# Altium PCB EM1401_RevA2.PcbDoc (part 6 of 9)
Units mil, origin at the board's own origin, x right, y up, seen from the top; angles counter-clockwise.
Board outline 7800 x 5300 mil, 6 copper layers (Top Layer, MidLayer1, MidLayer2, MidLayer3, MidLayer4, Bottom Layer), stack 16.8 mil thick; 751 components, 531 nets, 2554 pads, 1388 vias.
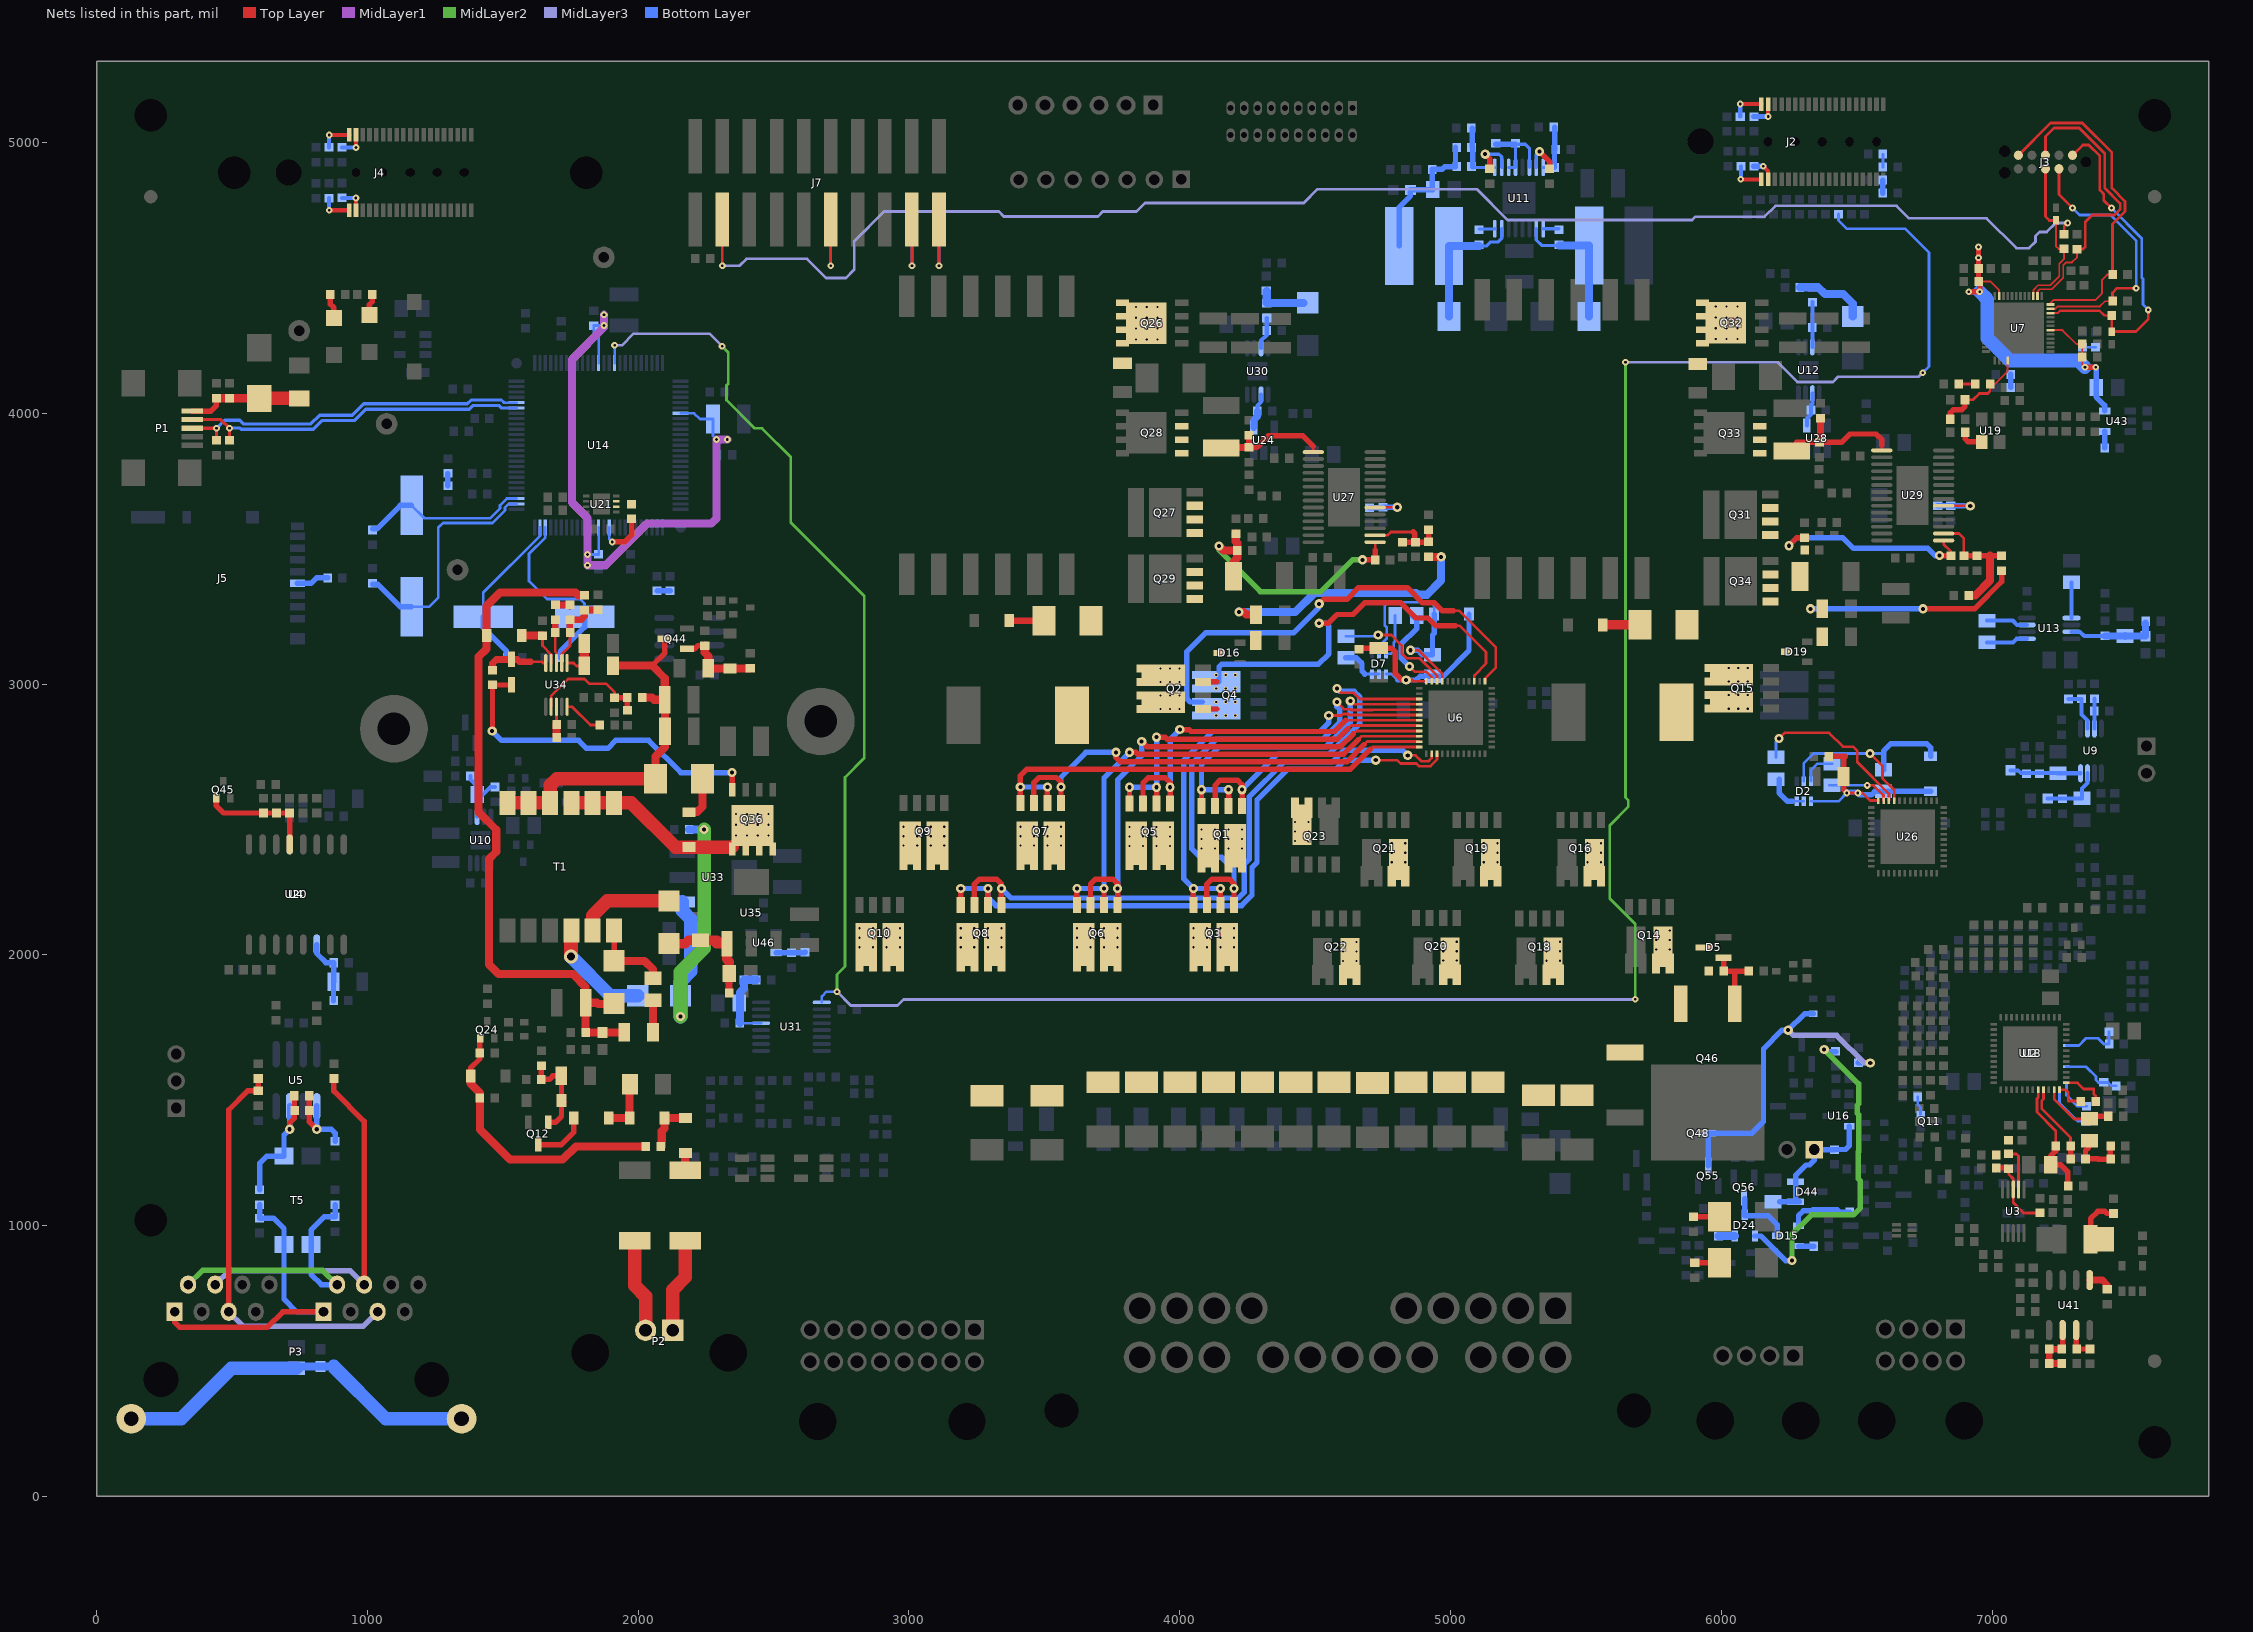
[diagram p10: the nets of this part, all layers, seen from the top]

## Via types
v1: diameter 25, hole 10, Top Layer to Bottom Layer, tented both sides, 275 vias
v2: diameter 16, hole 8, Top Layer to Bottom Layer, tented both sides, 240 vias
v3: diameter 34, hole 15, Top Layer to Bottom Layer, tented both sides, 158 vias
v4: diameter 34, hole 15, Top Layer to Bottom Layer, 154 vias
v5: diameter 34, hole 15, Top Layer to Bottom Layer, tented top, 95 vias
v6: diameter 34, hole 15, Top Layer to Bottom Layer, tented bottom, 89 vias
v7: diameter 25, hole 10, Top Layer to Bottom Layer, tented bottom, 75 vias
v8: diameter 25, hole 10, Top Layer to Bottom Layer, 62 vias
v9: diameter 28, hole 8, Top Layer to Bottom Layer, tented both sides, 60 vias
v10: diameter 24, hole 8, Top Layer to Bottom Layer, 53 vias
v11: diameter 25, hole 10, Top Layer to Bottom Layer, tented top, 28 vias
v12: diameter 50, hole 28, Top Layer to Bottom Layer, 28 vias
v13: diameter 25, hole 8, Top Layer to Bottom Layer, tented both sides, 18 vias
v14: diameter 50, hole 28, Top Layer to Bottom Layer, tented top, 12 vias
v15: diameter 25, hole 8, Top Layer to Bottom Layer, tented top, 9 vias
v16: diameter 20, hole 8, Top Layer to Bottom Layer, tented both sides, 9 vias
v17: diameter 24, hole 8, Top Layer to Bottom Layer, tented bottom, 4 vias
v18: diameter 24, hole 8, Top Layer to Bottom Layer, tented top, 4 vias
v19: diameter 28, hole 10, Top Layer to Bottom Layer, tented both sides, 3 vias
v20: diameter 35, hole 14, Top Layer to Bottom Layer, 3 vias
v21: diameter 50, hole 28, Top Layer to Bottom Layer, tented both sides, 2 vias
v22: diameter 50, hole 28, Top Layer to Bottom Layer, tented bottom, 2 vias
v23: diameter 30, hole 14, Top Layer to Bottom Layer, tented top, 2 vias
v24: diameter 28, hole 10, Top Layer to Bottom Layer, 1 vias
v25: diameter 35, hole 14, Top Layer to Bottom Layer, tented both sides, 1 vias
v26: diameter 35, hole 14, Top Layer to Bottom Layer, tented top, 1 vias

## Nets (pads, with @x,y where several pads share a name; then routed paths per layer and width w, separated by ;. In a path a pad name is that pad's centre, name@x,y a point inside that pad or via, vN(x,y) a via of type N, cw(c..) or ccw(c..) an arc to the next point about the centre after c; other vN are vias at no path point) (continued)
NCS_TS_: R284.2 U14.91 U31.1 | length 10656.6
  MidLayer2 w10: v8(2310,4248) 2332.65,4225.35 2332.65,4109.29 2326.5,4103.14 2326.5,4048.5 2430.5,3944.5 2458.02,3944.5 2563.5,3839.02 2563.5,3596.92 2835,3325.42 2835,2726.54 2764,2655.54 2764,1957.13 2734,1927.13 v11(2734,1864) ; v1(5646,4189) 5646,2581.43 5656,2571.43 5656,2546.57 5588,2478.57 5588,2209 5682,2115 v8(5682,1836)
  MidLayer3 w10: v1(1913,4251) 1940,4251 1983,4294 2264,4294 v8(2310,4248) ; v11(2734,1864) 2785,1813 2957.7,1813 2979.7,1835 5683,1835 v8(5682,1836) ; v1(5646,4189) 6208,4189 6281,4116 6412.12,4116 6431.12,4135 6729,4135 v8(6744,4150)
  Bottom Layer w10: v1(1913,4251) 1913.06,4250.94 U14.91@1913.06,4185.15 ; U31.1@2678.12,1824.57 2678.12,1846.12 2696,1864 v11(2734,1864) ; R284.2@6433,4735.88 6433,4712 6463,4682 6679.09,4682 6767,4594.09 6767,4173 v8(6744,4150)
NetC4_1: C4.1 C5.1 R19.1 U3.2 | length 174
  Top Layer w10: C4.1@7061.42,1265 7090.42,1265 7097.89,1257.53 U3.2@7097.89,1133.84
  Top Layer w20: C5.1@7014.98,1261.44 C5.1@7018.53,1265 ; C4.1@7057.86,1261.44 C4.1@7061.42,1265 C4.1@7060.91,1265.5
NetC4_2: C4.2 C251.1 R30.2 U3.3 | length 299.7
  Top Layer w10: C4.2@7061.42,1209.88 7061.42,1190 7078.21,1173.21 U3.3@7078.21,1133.84 7078.21,1085.21 7116.53,1046.88 R30.2@7177.42,1046.88
  Top Layer w20: C251.1@7018.53,1209.88 C251.1@7014.98,1213.44 7057.86,1213.44 C4.2@7061.42,1209.88
NetC8_1: C8.1 U2.37 | length 160.1
  Top Layer w10: U2.37@7274.55,1527.66 7315.39,1527.66 7338.05,1505 7375.42,1505 7375.42,1485.67 7382.42,1478.67 C8.1@7382.42,1458
NetC8_2: C8.2 U2.36 | length 116.7
  Top Layer w10: U2.36@7248.96,1502.07 7271.35,1502.07 7281.42,1492 7281.42,1460 7325.3,1460 C8.2@7327.3,1458 ; C8.2@7324.3,1462 C8.2@7325.3,1461
NetC10_1: C10.1 R271.1 U2.35 | length 270.2
  Top Layer w10: U2.35@7229.28,1502.07 7229.28,1468.14 7303.42,1394 C10.1@7360.42,1394
  Top Layer w20: C10.1@7355.41,1403.65 R271.1@7429.86,1403.65
NetC10_2: C10.2 C11.2 R279.1 R280.1 | length 221
  Top Layer w20: C10.2@7355.41,1323.65 7355.41,1287.65 7344.97,1277.21 C11.2@7344.97,1246.65 7390.76,1246.65 7391.42,1246 7436.42,1246 R280.1@7436.42,1294
NetC11_1: C11.1 R16.1 U2.33 | length 301.9
  Top Layer w10: U2.33@7189.91,1502.07 7189.91,1467.55 7183.92,1461.56 7183.92,1431.5 7289.97,1325.44 R16.1@7289.97,1294.65
  Top Layer w20: C11.1@7289.85,1246.65 7289.97,1246.77 R16.1@7289.97,1294.65
NetC12_1: C12.1 R16.2 R20.2 U2.32 | length 444.3
  Top Layer w10: U2.32@7170.22,1502.07 7170.22,1473.32 7165.92,1469.02 7165.92,1419.5 7234.85,1350.56 R16.2@7234.85,1294.65
  Top Layer w20: C12.1@7216.42,1231 7216.42,1257 7234.85,1275.44 R16.2@7234.85,1294.65 ; C12.1@7224.41,1226.79 7224.2,1226.99 7218.2,1226.99 C12.1@7216.2,1224.99 7253.42,1224.99 7279.74,1198.68 R20.2@7279.74,1147
NetC13_2: C13.2 C14.2 R21.2 U4.3 | length 249.7
  Bottom Layer w20: U4.3@813,2037.96 813,2005 847,1971 C13.2@875.44,1971 875.44,1901.44 C14.2@875,1901 R21.2@875,1831
NetC16_2: C16.2 D44.1 D44.2 PING_OFF.1 R278.2 U16.2 | length 511.6
  Bottom Layer w20: C16.2@6215,1088 D44.1@6274.69,1088 ; D44.1@6274.69,1087.6 D44.1@6274.69,1088 ; D44.1@6288.69,1087.6 6288.69,1088 D44.1@6274.69,1088 ; U16.2@6472.37,1367.6 6472.37,1294.37 6459.12,1281.12 R278.2@6418,1281.12 6418,1281 PING_OFF.1@6343,1281 6343,1241 6325.92,1223.92 6312.92,1223.92 6274.69,1185.69 D44.2@6274.69,1162.4 D44.1@6274.69,1088
NetC21_1: C21.1 C200.2 D6.1 F16.1 P1.1 | length 430.3
  Top Layer w20: P1.1@353.5,4008.35 422.35,4008.35 442,4028 C200.2@442,4055.44
  Top Layer w30: C200.2@442,4055.44 D6.1@490,4055.44 599.56,4055.44 C21.1@600,4055
  Top Layer w50: C21.1@600,4055 F16.1@748,4054.95 F16.1@748,4054.95
NetC24_1: C24.1 U14.52 Y1.1 | length 881.1
  Bottom Layer w10: Y1.1@1163,3286 1229,3286 1261.5,3318.5 1261.5,3577.5 1279,3595 1461.46,3595 1508,3641.54 1508,3652.5 1520.96,3665.46 U14.52@1550.85,3665.46
  Bottom Layer w20: C24.1@1019,3368 1039,3368 1121,3286 Y1.1@1163,3286
NetC25_1: C25.1 U14.53 Y1.2 | length 623.7
  Bottom Layer w10: Y1.2@1163,3660 1210,3613 1454,3613 1490,3649 1490,3659.96 1515.19,3685.15 U14.53@1550.85,3685.15
  Bottom Layer w20: C25.1@1019,3573 1035,3573 1122,3660 Y1.2@1163,3660
NetC27_1: C27.1 U14.48 Y2.1 | length 698.5
  Bottom Layer w10: U14.48@1657.15,3578.85 1657.15,3541.61 1597,3481.46 1597,3380.09 1663.09,3314 1785,3314 1802,3297 Y2.1@1802,3249
  Bottom Layer w20: C27.1@1714,3098 1714,3122 1802,3210 Y2.1@1802,3249
NetC28_1: C28.1 U14.49 Y2.2 | length 602.8
  Bottom Layer w10: Y2.2@1428,3249 1428,3337.91 1637.46,3547.38 U14.49@1637.46,3578.85
  Bottom Layer w20: Y2.2@1428,3249 1428,3208 1513.01,3122.99 C28.1@1513.01,3098
NetC34_2: C34.2 C37.1 L9.2 U9.7 | length 228.5
  Bottom Layer w15: L9.2@7205,2577 C34.2@7260,2577 7261,2578 C37.1@7332,2578 7332,2615 7352.41,2635.41 U9.7@7352.41,2670.65
NetC35_1: C35.1 C86.2 L6.1 R251.1 U9.8 | length 263.3
  Bottom Layer w15: L6.1@7068,2681.5 7096.5,2681.5 7107,2671 7175,2671 7241,2671 7241.35,2670.65 U9.8@7326.82,2670.65
NetC38_2: C38.2 R63.2 U11.3 U11.4 U11.6 | length 312.4
  Bottom Layer w12: U11.3@5214.61,4908.19 U11.4@5240.2,4908.19 C38.2@5240.2,4993.8 ; C38.2@5240,4994 C38.2@5240.2,4993.8 ; U11.6@5291.39,4908.19 5291.39,4978.61 5276.2,4993.8 C38.2@5240.2,4993.8
  Bottom Layer w20: R63.2@5167,4994 C38.2@5240,4994
NetC39_2: C39.2 U43.4 | length 61.7
  Bottom Layer w20: U43.4@7415.76,3933.6 7415.76,3872.24 C39.2@7416,3872
NetC45_1: C45.1 C47.1 C48.2 U14.7 U14.38 U14.88 | length 2534.3
  MidLayer1 w30: v1(1874,4364) v1(1874,4324) 1874,4318 1755,4199 1755,3671 1813,3613 v1(1813,3478.85) v1(1813,3438.85) 1878.85,3438.85 2033,3593 2270,3593 2289,3612 v1(2289,3903) v1(2329,3903)
  Bottom Layer w10: v1(1813,3438.85) v1(1813,3478.85) C45.1@1854,3478.85 U14.38@1854,3578.85 ; U14.88@1854,4185.15 1854,4277 1836,4295 C48.2@1836,4324 v1(1874,4324) 1874,4362 1872,4364 v1(1874,4364) ; U14.7@2157.15,4000.11 2206.89,4000.11 2228,3979 C47.1@2276,3979 2276,3916 v1(2289,3903) v1(2329,3903)
NetC46_1: C46.1 R22.1 | length 48.1
  Bottom Layer w10: R22.1@6596.76,4909 6597,4909.24 C46.1@6597,4957
NetC49_1: C49.1 R36.1 | length 48
  Bottom Layer w20: R36.1@2070,3344 2117.88,3344 C49.1@2118,3343.88
NetC51_2: C51.2 R146.2 | length 48
  Bottom Layer w20: R146.2@7068.56,4096 C51.2@7068.56,4144
NetC53_1: C53.1 U13.1 | length 152
  Bottom Layer w15: C53.1@6981.57,3154.07 7077.48,3154.07 7090.79,3167.38 U13.1@7128.01,3167.38
NetC53_2: C53.2 U13.3 | length 152.9
  Bottom Layer w15: C53.2@6981.57,3234.07 7076.35,3234.07 7091.86,3218.56 U13.3@7128.01,3218.56
NetC54_2: C54.2 C84.2 L4.1 R96.2 U13.7 | length 329.1
  Bottom Layer w15: U13.7@7293.36,3192.97 7325.45,3192.97 7340.41,3178.01 R96.2@7416.64,3178.01
  Bottom Layer w25: R96.2@7416.64,3178.01 C54.2@7491.2,3178.01 ; C54.2@7491.64,3177.57 7566.43,3177.57 L4.1@7567,3177 C84.2@7567,3226
  Bottom Layer w30: C54.2@7491.64,3177.57 C54.2@7492,3177.21
NetC55_2: C55.2 R147.2 | length 45.3
  Bottom Layer w20: R147.2@1297,3732.56 C55.2@1297,3777.88
NetC56_2: C56.2 U13.5 | length 131.9
  Bottom Layer w15: U13.5@7293.36,3244.15 7293.36,3375.95 C56.2@7293.42,3376
NetC57_2: C57.2 P3.A2 P3.B2 R40.2 T5.1 | length 1023.9
  MidLayer2 w20: P3.A2@338,782 391,835 835,835 P3.B2@888,782
  Bottom Layer w20: R40.2@881,1078 C57.2@881,1033 841,1033 792,984 T5.1@792,930.23 792,820 830,782 P3.B2@888,782
NetC58_2: C58.2 R150.1 R216.1 U10.2 | length 241.5
  Bottom Layer w15: R150.1@1380.12,2660 1380.12,2646.88 1405.2,2621.8 C58.2@1405.2,2585 ; U10.2@1405.2,2510.66 C58.2@1405.2,2584.8 ; R216.1@1472,2620 1454,2620 1419,2585 C58.2@1405.2,2585 ; C58.2@1405.2,2584.8 C58.2@1405.2,2585 ; C58.2@1405.2,2584.8 1405,2585 C58.2@1405.2,2585
NetC59_1: C59.1 P3.A1 P3.B1 R41.2 T5.2 | length 1200.1
  Top Layer w20: P3.A1@288,682 288,644 307,625 631,625 688,682 P3.B1@838,682
  Bottom Layer w20: R41.2@602,1077 C59.1@602,1028 653,1028 692,989 T5.2@692,930.23 692,729 739,682 P3.B1@838,682
NetC61_1: C61.1 R39.1 | length 48
  Bottom Layer w20: R39.1@6596.76,4813 6596.88,4813.12 C61.1@6596.88,4861
NetC62_2: C62.2 R149.2 | length 48
  Bottom Layer w10: C62.2@7334,4243.88 R149.2@7382,4243.88
NetC63_2: C63.2 J5.4 | length 119.6
  Bottom Layer w20: J5.4@741.56,3371.94 791.94,3371.94 812,3392 C63.2@852.88,3392
NetC64_1: C64.1 C248.2 R125.1 | length 173.4
  Top Layer w20: C64.1@7363.59,952 7363.86,952.27 7363.86,1026.44 7390.3,1052.88 7416.53,1052.88 7424.53,1044.88 R125.1@7448.42,1044.88
NetC66_2: C66.2 D45.2 Q44.1 R145.1 R148.2 | length 315.7
  Top Layer w20: Q44.1@2180.09,3130.6 2209.6,3130.6 2221.44,3142.44 R145.1@2246,3142.44
  Top Layer w30: R145.1@2246,3142.44 2246,3117 2259,3104 C66.2@2259,3058 2338.94,3058 D45.2@2339,3058.06 2413.94,3058.06 R148.2@2414,3058
NetC69_1: C69.1 Q11.2 | length 67.6
  Bottom Layer w10: C69.1@6726,1475 6726,1447 6736.01,1436.99 Q11.2@6736.01,1411.59
NetC70_1: C70.1 U18.37 | length 176.2
  Bottom Layer w10: U18.37@7248.96,1502.07 7248.96,1453.45 7316.98,1385.44 C70.1@7348.42,1385.44
NetC70_2: C70.2 U18.36 | length 136.8
  Bottom Layer w10: U18.36@7274.55,1527.66 7274.55,1481.86 7315.86,1440.56 C70.2@7348.42,1440.56
NetC73_2: C73.2 R134.2 U18.33 | length 220.5
  Bottom Layer w10: U18.33@7274.55,1586.71 7347.7,1586.71 7383.42,1551 7383.42,1538 7392.53,1528.88 R134.2@7412.42,1528.88 7428.53,1528.88 7440.76,1516.65 C73.2@7458.41,1516.65
NetC75_1: C75.1 R131.2 U18.29 | length 222.8
  Bottom Layer w10: U18.29@7274.55,1665.45 7320.66,1665.45 7347.21,1692 7391.42,1692 7412.42,1671 C75.1@7431.86,1671 7431.86,1716.21 R131.2@7431.41,1716.65
NetC82_2: C82.2 C162.1 D26.1 D27.2 L3.1 R217.1 R227.2 | length 2572.7
  Top Layer w30: 1778,3328 1777.44,3328.56 ; R227.2@1802.5,3328.56 1777.44,3328.56 ; D26.1@1911,1820.52 1909.48,1819 1852,1819 1848,1823 C162.1@1806,1823 ; R217.1@1948.7,1714 1948.2,1713.5 L3.1@1868,1713.5 1867.5,1713 C82.2@1806,1713 C162.1@1806,1823 ; 1777.44,3328.56 1768,3338 1489.5,3338 1440,3288.5 1440,3130 1411,3101 1411,2527 1476,2462 1476,2381 1449,2354 1449,1964 1484,1929 1759,1929 1806,1882 C162.1@1806,1823
NetC88_2: C88.2 C92.1 C96.2 L8.1 L11.1 R152.1 | length 542.5
  Bottom Layer w20: L11.1@4810.93,4618 4810.93,4761.93 4852,4803 L8.1@4852,4825 4853,4826 C92.1@4934,4826 4933,4827 C88.2@4933,4901 4969,4901 4979,4911 5018.5,4911 C96.2@5018.5,4982
NetC90_1: C90.1 U11.16 | length 57.8
  Bottom Layer w12: C90.1@5106,4681 5162.62,4681 U11.16@5163.43,4681.81
NetC90_2: C90.2 D8.1 L11.2 U11.15 | length 502.4
  Bottom Layer w12: C90.2@5106,4618.01 5134.01,4618.01 5149,4633 5176,4633 5189.02,4646.02 U11.15@5189.02,4681.81
  Bottom Layer w30: D8.1@4994,4358 L11.2@4994,4618 C90.2@5105.99,4618
NetC91_1: C91.1 D1.1 L10.1 U11.10 | length 509.9
  Bottom Layer w12: U11.10@5316.98,4681.81 5316.98,4640.02 5337,4620 C91.1@5402.99,4620
  Bottom Layer w25: C91.1@5401,4618.01 C91.1@5402.99,4620
  Bottom Layer w30: C91.1@5402.99,4620 L10.1@5512,4620 D1.1@5512.01,4358
NetC91_2: C91.2 U11.9 | length 58.8
  Bottom Layer w12: U11.9@5342.57,4681.81 5400.19,4681.81 C91.2@5401,4681
NetC94_2: C94.2 U11.7 | length 139.6
  Top Layer w20: v3(5329,4967) 5366,4930 C94.2@5366,4906.5
  Bottom Layer w12: U11.7@5316.98,4908.19 5316.98,4954.98 v3(5329,4967)
NetC95_2: C95.2 U11.2 | length 160.5
  Top Layer w20: v3(5128,4957) 5145,4940 C95.2@5145,4907.5
  Bottom Layer w12: v3(5128,4957) 5179,4957 5189.02,4946.98 U11.2@5189.02,4908.19
NetC96_1: C96.1 R152.2 R153.2 U11.1 | length 225.3
  Bottom Layer w12: R152.2@5081.5,4911 5084.31,4908.19 U11.1@5163.43,4908.19
  Bottom Layer w20: R153.2@5081,5053 5081,4982.5 5081.5,4982 R152.2@5081.5,4911
NetC97_2: C97.2 R64.2 R187.2 U11.8 | length 190.7
  Bottom Layer w12: U11.8@5342.57,4908.19 5383.81,4908.19 R64.2@5384,4908
  Bottom Layer w20: R64.2@5384,4908 5384,4972.5 5384.5,4972.99 R187.2@5384.5,5057
NetC98_1: C98.1 C241.2 C242.2 C243.2 C244.2 U7.18 U7.35 U43.5 | length 1423.6
  Top Layer w7: C242.2@6954,4487 6992.79,4487 7026.13,4453.65 U7.35@7026.13,4434.09 ; U7.18@7216.09,4307.13 7259.96,4307.13 7311.09,4256 C244.2@7333,4256 C243.2@7333,4208 7333,4180 v1(7343,4170)
  Top Layer w20: v1(6914,4449) v1(6954,4449) C242.2@6954,4487 ; v1@6949.44,4574.56 v1@6950,4574 ; C242.2@6950,4487 C241.2@6950,4535 v1@6950,4574 ; v1(6950,4614.56) v1(6950,4574.56) v1@6950,4574 ; v1(7343,4170) v1(7383,4170)
  Bottom Layer w20: v1(6914,4449) v1(6954,4449) ; v1(7343,4170) v1(7383,4170) 7384,4169 C98.1@7384,4096 7384,4061 7415.76,4029.24 U43.5@7415.76,4008.4
  Bottom Layer w50: v1(6954,4449) 6983,4420 6983,4277 7065,4195 7318,4195 v1(7343,4170)
NetC100_2: C100.2 L1.2 P3.10 | length 1379.9
  Bottom Layer w30: C100.2@738,473 745,480 L1.2@827,480 875,480
  Bottom Layer w50: P3.10@128,287 312,287 498,473 C100.2@738,473 ; 875,480 1068,287 P3.10@1348,287
NetC101_2: C101.2 U19.4 | length 90.8
  Top Layer w20: C101.2@6901,3930 6901,3905 6911.5,3894.5 U19.4@6962.5,3894.5
NetC102_2: C102.2 D10.2 Q12.1 R37.1 R176.2 | length 348
  Top Layer w20: R176.2@1643,1591 1642.56,1590.56 R37.1@1642.56,1540 1672,1540 1685,1553 C102.2@1716,1553 1716.94,1552.06 D10.2@1716.94,1463 ; Q12.1@1668.4,1381.68 1694.68,1381.68 1716.94,1403.94 D10.2@1716.94,1463 ; D10.2@1724.54,1455.4 D10.2@1716.94,1463
NetC106_1: C106.1 D51.1 Q24.1 R83.1 R215.1 | length 1040.9
  Top Layer w20: D51.1@1381.53,1553 1381.53,1582.53 1415.44,1616.44 R215.1@1415.44,1638 1415.44,1690.04 Q24.1@1417.41,1692.01
  Top Layer w30: D51.1@1381.53,1553 1381.53,1524.47 1415.44,1490.56 C106.1@1415.44,1472 1415.44,1355.56 1527,1244 1721,1244 1770,1293 R83.1@2024.5,1293
NetC107_2: C107.2 Q45.1 R151.2 R223.1 U20.13 | length 426.2
  Top Layer w20: Q45.1@441.82,2579 441.82,2551.18 469,2524 R223.1@617,2524 C107.2@665,2524 R151.2@713,2524 U20.13@713,2408.04
NetC113_1: C113.1 R82.1 | length 57
  Top Layer w10: R82.1@6881,4108 C113.1@6938,4108
NetC113_2: C113.2 R85.1 R86.2 U7.4 | length 370
  Top Layer w7: C113.2@6993.12,4108 7010.7,4108 7057.63,4154.93 U7.4@7057.63,4195.91
  Top Layer w10: R85.1@6900,4050 6930,4050 6953,4073 6984,4073 6993.12,4082.12 C113.2@6993.12,4108
  Top Layer w20: R86.2@6845.44,3978 6845.44,4001.44 6856.73,4012.73 6887.73,4012.73 6900,4025 R85.1@6900,4050
NetC114_1: C114.1 U14.36 | length 199.9
  Top Layer w20: v1(1904,3525) 1950,3525 1976,3551 C114.1@1976,3609.88
  Bottom Layer w10: U14.36@1893.37,3578.85 1893.37,3535.63 v1(1904,3525)
NetC114_2: C114.2 U21.2 U21.3
NetC117_2: C117.2 R246.1 U9.2 | length 162.6
  Bottom Layer w15: C117.2@7282,2945 7282.44,2945.44 R246.1@7330,2945.44 ; R246.1@7329.56,2941 7330,2940.56 7330,2887.94 7352.41,2865.53 U9.2@7352.41,2836
NetC125_2: C125.2 Q26.5 Q26.6 Q26.7 Q26.8 Q26.9
  other v9: 3838.5,4273 3878.5,4273 3918.5,4273 3838.5,4313 3878.5,4313 3918.5,4313 3838.5,4353 3878.5,4353 3918.5,4353 3838.5,4393 3878.5,4393 3918.5,4393
NetC126_1: C126.1 C127.1 D16.3 L5.2 Q2.5 Q2.6 Q2.7 Q2.8 R247.1 Zener1.2 | length 1004
  Top Layer w30: v4(4218.42,3266) 4236,3266 4245.54,3256.46 C126.1@4281.39,3256.46 ; R247.1@4918.42,3469.88 4918.53,3470 v3(4965.42,3470)
  Bottom Layer w30: v4@4219.42,3267 v4(4218.42,3266) 4426.42,3266 4497.42,3337 4872.85,3337 4879.85,3330 4912.98,3330 4965.42,3382.43 v3(4965.42,3470)
  other v2: 3929.09,2908 3964.09,2908 3999.09,2908 3929.09,2958 3964.09,2958 3999.09,2958 3929.09,3008 3964.09,3008 3999.09,3008 3929.09,3058 3964.09,3058 3999.09,3058
NetC129_1: C129.1 D17.2 R171.2 | length 181.2
  Bottom Layer w30: R171.2@4321.42,4452 C129.1@4321.42,4407.12 4456.53,4407.12 D17.2@4457.42,4408
NetC129_2: C129.2 R48.2 U30.7 | length 118.2
  Bottom Layer w15: U30.7@4300.21,4240.63 4300.21,4268.8 4321.42,4290 R48.2@4321.42,4306 ; R48.2@4321.42,4308 C129.2@4321.42,4352
NetC135_2: C135.2 Q32.5 Q32.6 Q32.7 Q32.8 Q32.9
  other v9: 5979.5,4274 6019.5,4274 6059.5,4274 5979.5,4314 6019.5,4314 6059.5,4314 5979.5,4354 6019.5,4354 6059.5,4354 5979.5,4394 6019.5,4394 6059.5,4394
NetC136_1: C136.1 C137.1 D19.3 L7.2 Q15.5 Q15.6 Q15.7 Q15.8 R248.1 Zener2.2 | length 789.3
  Top Layer w20: v4(6745.42,3278) 6935.42,3278 7035.42,3378 R248.1@7035.42,3419.44
  Bottom Layer w20: v5(6329,3278) v4(6745.42,3278)
  other v2: 6027.61,2909.24 6062.61,2909.24 6097.61,2909.24 6027.61,2959.24 6062.61,2959.24 6097.61,2959.24 6027.61,3009.24 6062.61,3009.24 6097.61,3009.24 6027.61,3059.24 6062.61,3059.24 6097.61,3059.24
NetC139_1: C139.1 D20.2 R189.2 | length 267.6
  Bottom Layer w30: R189.2@6290.42,4465 6290.98,4465.56 C139.1@6336.42,4465.56 6356.97,4465.56 6382.53,4440 6450.42,4440 6485.42,4405 D20.2@6485.42,4357.74
NetC139_2: C139.2 R49.2 U12.7 | length 165.9
  Bottom Layer w15: U12.7@6336.21,4244.63 6336.42,4244.83 R49.2@6336.42,4317 C139.2@6336.42,4410.44
NetC144_1: C144.1 C145.1 R104.2 R105.1 U31.13 | length 290.6
  Bottom Layer w10: C144.1@2375.42,1748 2453.51,1748 U31.13@2453.71,1747.8
  Bottom Layer w30: C144.1@2375.42,1748 2375.42,1861.42 2390.42,1876.42 R104.2@2390.42,1908 R105.1@2436.42,1908
NetC155_1: C155.1 C156.1 D3.2 Q44.3 R212.1 R243.2 T1.4 T1.5 T1.6 | length 1422.9
  Top Layer w20: 2052,3068 2097.42,3113.42 Q44.3@2097.42,3168
  Top Layer w30: R212.1@1907.15,3068 2052,3068 2098.27,3021.73 C156.1@2098.27,2942 ; R243.2@2015.56,2950 2051,2950 2059,2942 C156.1@2098.27,2942 ; D3.2@2063.98,2650 2063.98,2732.98 2098.91,2767.91 C155.1@2098.91,2825.49 2098.91,2941.36 C156.1@2098.27,2942
  Top Layer w50: T1.6@1517.15,2561.24 T1.5@1595.89,2561.24 T1.4@1674.63,2561.24 1674.63,2625.63 1699,2650 D3.2@2063.98,2650
NetC157_2: C157.2 R212.2 U34.1 | length 148.7
  Top Layer w10: U34.1@1737.57,3077.73 1761.77,3077.73 1772.5,3067 R212.2@1800.85,3067
  Top Layer w35: R212.2@1800.85,3067 R212.2@1800.85,3068 C157.2@1800.85,3148
NetC158_1: C158.1 D23.1 R213.1 R214.2 U33.1 | length 1234.1
  MidLayer2 w50: v6(2156.42,1772) 2156.42,1937.42 2243.42,2024.42 v5(2243.42,2463)
  Bottom Layer w30: R213.1@2188.42,2463 v5(2243.42,2463)
  Bottom Layer w50: v6(2156.42,1772) D23.1@2156.42,1849 2156.42,1902 2194.42,1940 C158.1@2194.42,1994 R214.2@2194.42,2090 2194.42,2132 2163.42,2163 U33.1@2163.42,2195.45
NetC160_1: C160.1 D27.1 U34.4 | length 190.7
  Top Layer w10: C160.1@1646.5,3178.44 1646.5,3142 1678.52,3109.98 U34.4@1678.52,3077.73
  Top Layer w30: D27.1@1570,3179 1645.94,3179 C160.1@1646.5,3178.44
NetC161_1: C161.1 R249.1 U9.3 | length 109.9
  Bottom Layer w15: U9.3@7378,2836 C161.1@7378,2900 R249.1@7378,2945.88
NetC163_1: C163.1 D26.2 T1.12 | length 303.7
  Top Layer w20: T1.12@1910.85,2090.76 1911,2090.61 D26.2@1911,1978
  Top Layer w30: D26.2@1911,1978 2024,1978 2055,1947 C163.1@2055,1913
NetC163_2: C163.2 R217.2 | length 119
  Top Layer w30: R217.2@2055,1714 C163.2@2055,1833
NetC164_1: C164.1 D28.1 R218.1 R220.2 U35.1 | length 424.9
  Top Layer w25: R218.1@2335.86,1860 2335.86,1931.44 R220.2@2336.42,1932
  Top Layer w35: D28.1@2114.1,2041.76 2173.18,2041.76 2185.42,2054 C164.1@2230.42,2054 2275.42,2054 ; 2291.42,2054 2275.42,2054 ; R220.2@2336.42,1932 2336.42,1975 2327.86,1983.55 U35.1@2327.86,2040.83 2288.59,2040.83 2275.42,2054
NetC166_2: C166.2 R219.2 R243.1 U34.7 | length 434.8
  Top Layer w10: U34.7@1678.52,2916.32 1678.52,2956.02 1741.5,3019 1801.5,3019 1819.5,3001 1882.5,3001 1912.5,2971 C166.2@1912.5,2950
  Top Layer w20: C166.2@1912.5,2950 R243.1@1960.44,2950 1960.44,2904.44 R219.2@1960,2904
NetC167_1: C167.1 R221.1 U34.8 | length 110.6
  Top Layer w10: C167.1@1698.2,2851 U34.8@1698.2,2916.32
  Top Layer w30: C167.1@1698.2,2851 1698.2,2806.74 R221.1@1698.94,2806
NetC168_2: C168.2 U34.10 | length 149.3
  Top Layer w10: U34.10@1737.57,2916.32 1756.18,2916.32 1823.5,2849 C168.2@1858.94,2849
NetC169_1: C169.1 C170.1 R227.1 R228.2 U34.2 | length 291
  Top Layer w10: U34.2@1717.89,3077.73 1717.89,3110.39 1748.56,3141.06 C169.1@1748.56,3186
  Top Layer w25: C170.1@1747.5,3228.44 1747.5,3192.06 C169.1@1748.56,3191 ; C170.1@1747.5,3237.44 1788.44,3237.44 1802.5,3251.5 R227.1@1802.5,3273.44 1850.5,3273.44 R228.2@1851.5,3274.44
NetC169_2: C169.2 R226.2 U34.3 | length 161.8
  Top Layer w10: C169.2@1693.44,3191 1693.5,3190.94 1693.5,3121 1698.2,3116.3 U34.3@1698.2,3077.73
  Top Layer w25: C169.2@1693.5,3191.06 1694,3191.56 R226.2@1694,3237.44
NetC170_2: C170.2 R226.1 | length 54.7
  Top Layer w25: R226.1@1694.5,3292.56 1743.5,3292.56 C170.2@1747.5,3288.56
NetC196_1: C196.1 R54.1 U27.6 | length 184.6
  Top Layer w10: U27.6@4721.62,3652.15 4722.48,3653 v5(4803.42,3653)
  Bottom Layer w20: C196.1@4701.42,3652 4749.98,3652 R54.1@4750.42,3652.44 4802.86,3652.44 v5(4803.42,3653)
NetC197_1: C197.1 R53.1 U29.6 | length 196.5
  Top Layer w10: U29.6@6821.05,3658.29 6919.12,3658.29 v5(6919.42,3658)
  Bottom Layer w20: C197.1@6799.42,3658 R53.1@6847.42,3658 6897.42,3658
NetC205_1: C205.1 R34.1 U41.3 | length 120.2
  Top Layer w20: R34.1@7310.41,544.56 U41.3@7310.41,614.14 ; R34.1@7311.98,544 7312.53,544.56 C205.1@7362.42,544.56
NetC207_2: C207.2 C_Vstack1.2 D7.4 D13.2 R23.1 U6.48 | length 838.9
  Top Layer w10: v3(4836.42,3015) 4859.42,3015 4864.31,3010.1 U6.48@4910.65,3010.1
  Top Layer w20: R23.1@4665.42,3133 C207.2@4735.42,3133 4782.42,3133 4796.42,3119 4796.42,3038.58 4820,3015 v3(4836.42,3015)
  Bottom Layer w10: D7.4@4762,3037 4782.42,3037 4804.42,3015
  Bottom Layer w20: 4804.42,3015 v3(4836.42,3015) 4873.42,3015 4887.42,3029 C_Vstack1.2@4933.42,3029 4973.42,3029 5068.35,3123.94 D13.2@5068.35,3259
NetC209_2: C209.2 C_Vstack2.2 D2.4 D14.2 R29.1 U26.48 | length 794.8
  Top Layer w10: v1(6463.42,2598) v1(6504.42,2598) 6521.42,2598 6549.56,2569.86 U26.48@6579.65,2569.86
  Top Layer w20: R29.1@6400.91,2733 6458.42,2733 6451.57,2726.15 C209.2@6451.57,2659 6451.57,2609.85 v1(6463.42,2598)
  Bottom Layer w10: D2.4@6331,2567 6432.42,2567 v1(6463.42,2598)
  Bottom Layer w20: v1(6463.42,2598) 6466.92,2601.5 6500.92,2601.5 v1(6504.42,2598) 6511.42,2591 6553.91,2591 6566.91,2604 C_Vstack2.2@6599.42,2604 6599.95,2604.53 D14.2@6773.42,2604.53
NetC217_1: C217.1 R236.1 R237.1 R247.2 U27.2 | length 328.5
  Top Layer w10: U27.2@4721.62,3549.78 4767.2,3549.78 4779.42,3562 4862,3562
  Top Layer w20: C217.1@4822.42,3524 4822.98,3524.56 R236.1@4870.42,3524.56 ; 4862,3562 4868.42,3555.58 4868.42,3526.56 R236.1@4870.42,3524.56 ; R237.1@4919,3570.44 4919,3525.58 R247.2@4918.42,3525 4917.98,3524.56 R236.1@4870.42,3524.56
NetC218_1: C218.1 R238.1 R239.1 R248.2 U29.2 | length 475.7
  Top Layer w10: U29.2@6821.05,3555.93 6877.49,3555.93 6895.92,3537.5 C218.1@6895.92,3474.56
  Top Layer w20: C218.1@6895.92,3474.56 R239.1@6943.92,3474.56 6992.98,3474.56 R248.2@7035.42,3474.56
  Top Layer w30: R238.1@6917.41,3327 6937.75,3327 6992.98,3382.23 6992.98,3474.56
NetC225_1: C225.1 U24.4 U30.2 | length 132.6
  Bottom Layer w15: C225.1@4286.86,4009 4286.86,4028.33 4300.62,4042.1 U30.2@4300.62,4069.37
  Bottom Layer w25: U24.4@4273.42,3948 4273.42,3975 4286.86,3988.44 C225.1@4286.86,4009
NetC226_1: C226.1 U12.2 U28.4 | length 126.2
  Bottom Layer w15: U28.4@6316.01,3955.49 6316.01,3980.6 6331.3,3995.88 C226.1@6331.3,4012 6331.3,4030.88 6336.21,4035.8 U12.2@6336.21,4073.37
NetC232_2: C232.2 Q27.1 Q27.2 Q27.3 Q29.1 Q29.2 Q29.3 R173.1 R174.1 R180.2 U27.1 | length 1012.7
  Top Layer w10: 4721.62,3494.79 U27.1@4721.62,3524.19
  Top Layer w20: v5(4675.42,3459) C232.2@4721.42,3459 ; C232.2@4721.42,3456 C232.2@4721.42,3459 ; 4721.62,3494.79 4721.62,3459.21 C232.2@4721.42,3459
  Top Layer w30: v4(4145,3510) 4162,3493 R180.2@4212.36,3493 ; R174.1@4198.43,3398 4198.43,3451.43 4212.36,3465.36 R180.2@4212.36,3493 ; R173.1@4207.42,3555.88 4207,3555.47 4207,3526 4212.36,3520.64 R180.2@4212.36,3493
  MidLayer2 w20: v4(4145,3510) 4145,3494.42 4297.92,3341.5 4520.92,3341.5 4638.42,3459 v5(4675.42,3459)
NetC233_1: C233.1 Q28.1 Q28.2 Q28.3 R177.1 R179.2 U27.15 | length 439.2
  Top Layer w10: U27.15@4493.28,3856.87 4493.28,3878.14
  Top Layer w20: R179.2@4156.42,3856.26 R179.2@4156.56,3856.12 ; R177.1@4257.3,3875 R177.1@4256.42,3874.12 4284.53,3874.12 4327.92,3917.5 4453.92,3917.5 4493.28,3878.14
  Top Layer w25: R179.2@4156.42,3874.12 R177.1@4256.42,3874.12 C233.1@4256.42,3919.44
NetC234_2: C234.2 Q31.1 Q31.2 Q31.3 Q34.1 Q34.2 Q34.3 R191.1 R192.1 R198.2 U29.1 | length 774.6
  Top Layer w10: U29.1@6821.05,3530.34 6821.05,3516.37 6847.92,3489.5 C234.2@6847.92,3474.56
  Top Layer w20: v4(6250,3511) 6279.88,3540.88 R191.1@6307.42,3540.88 ; v5(6805.86,3474.56) C234.2@6847.92,3474.56
  Bottom Layer w20: v4(6250,3511) 6280,3541 6448.42,3541 6488.42,3501 6763.42,3501 6789.86,3474.56 v5(6805.86,3474.56)
NetC235_2: C235.2 Q33.1 Q33.2 Q33.3 R195.1 R197.2 U29.15 | length 495.6
  Top Layer w10: U29.15@6592.7,3863.02 6592.7,3882.71
  Top Layer w20: R197.2@6263.42,3877.26 6278.72,3892.56 R195.1@6362.42,3892.56 6443.76,3892.56 6474.7,3923.5 6571.77,3923.5 6592.7,3902.57 6592.7,3882.71 ; R197.2@6295.42,3862.26 R197.2@6295.68,3862
  Top Layer w25: R197.2@6266.42,3879.26 R197.2@6271.68,3874 ; R195.1@6362.42,3892.56 6366.42,3896.56 C235.2@6366.42,3981.62 C235.2@6366.16,3981.36
NetC238_1: C238.1 R26.1 R283.2 U5.5 | length 325.4
  Top Layer w20: R283.2@785.5,1479.8 785.5,1425.35 C238.1@786.06,1424.8 786.06,1382.94 v4(813,1356)
  Bottom Layer w20: U5.5@813,1442.51 U5.5@813,1440.54 v4(813,1356) 867,1356 881,1342 R26.1@881,1312.12
NetC238_2: C238.2 R41.1 R283.1 T5.3 U5.7 | length 524.7
  Top Layer w20: v4(713,1356) 713,1379 730.94,1396.94 C238.2@730.94,1424.8 730.94,1479.24 R283.1@730.38,1479.8
  Bottom Layer w20: R41.1@602,1132.12 602,1230 629,1257 T5.3@692,1257 692,1335 v4(713,1356) U5.7@713,1440.54 U5.7@713,1442.51
NetC240_1: C240.1 R240.2 U46.5 | length 106.8
  Bottom Layer w20: U46.5@2510.42,2008 R240.2@2566,2008 2614.53,2008 C240.1@2616.42,2009.88
NetC249_1: C249.1 R34.2 R100.2 R235.1 U41.2 | length 216.7
  Top Layer w20: R34.2@7256.86,544 R34.2@7257.42,544.56 ; R34.2@7260.41,544 U41.2@7260.41,614.14
  Top Layer w25: R34.2@7256.86,544 R235.1@7210.98,544 R100.2@7210.98,491 C249.1@7257.86,491
NetC250_2: C250.2 U41.5 | length 88.8
  Top Layer w25: U41.5@7360.41,799.17 7407.83,799.17 7425.42,781.58 C250.2@7425.42,765.12
NetC_Vstack1_1: C_Vstack1.1 D7.2 D13.1 U6.45 | length 827.8
  Top Layer w10: v4(4852.42,3125) 4881.92,3125 4969.7,3037.21 U6.45@4969.7,3010.1
  Bottom Layer w10: D7.2@4736,3112 4736,3140 4764.42,3168.42 4764.42,3209 4757.42,3216 4757.42,3290.88 4768.53,3302 4925.42,3302 4939.42,3288 D13.1@4939.42,3259
  Bottom Layer w20: v4@4860.42,3125 4879.42,3125 4895.42,3109 C_Vstack1.1@4933.42,3109 4933.42,3181 4939.42,3187 D13.1@4939.42,3259
NetC_Vstack2_1: C_Vstack2.1 D2.2 D14.1 U26.45 | length 881.3
  Top Layer w10: v4(6549.42,2744) 6595.42,2698 6595.42,2652 6638.7,2608.71 U26.45@6638.7,2569.86
  Bottom Layer w10: D2.2@6305,2642 6305,2708 6341,2744 v4(6549.42,2744) 6590.42,2744 6599.42,2753
  Bottom Layer w20: C_Vstack2.1@6599.42,2684 6599.42,2753 6625.42,2779 6759.42,2779 6773.42,2765 D14.1@6773.42,2733.47
NetCEXT1_1: CEXT1.1 D7.3 | length 166.4
  Bottom Layer w10: D7.3@4762,3112 4780,3112 4790,3122 4790,3152.58 4794.99,3157.58 4794.99,3253.58 CEXT1.1@4795.42,3254
NetCEXT1_2: CEXT1.2 U6.47 | length 345.2
  Top Layer w10: v4(4848.42,3065) 4867.42,3046 4909.87,3046 4930.33,3025.53 U6.47@4930.33,3010.1
  Bottom Layer w20: v4(4848.42,3065) 4817.42,3096 4817.42,3147.47 4817.99,3148.05 4817.99,3148.58 4875.42,3206 4875.42,3237 CEXT1.2@4859.42,3253
NetCEXT2_1: CEXT2.1 D7.5 D7.6 | length 163.8
  Bottom Layer w10: 4684,3037 D7.6@4710,3037 D7.5@4736,3037
  Bottom Layer w20: CEXT2.1@4613.42,3097 4652,3097 4673,3076 4673,3048 4684,3037
NetCEXT2_2: CEXT2.2 U6.46 | length 438.5
  Top Layer w10: v3(4733,3181) 4781.42,3181 4819.42,3143 4819.42,3114 4838.42,3095 4886.32,3095 4950.02,3031.31 U6.46@4950.02,3010.1
  Bottom Layer w10: CEXT2.2@4613.42,3177 4729,3177 v3(4733,3181)
NetCEXT3_1: CEXT3.1 D2.3 | length 127.9
  Bottom Layer w10: D2.3@6331,2642 6331,2682 6355,2706 CEXT3.1@6409,2706
NetCEXT3_2: CEXT3.2 U26.47 | length 234.8
  Top Layer w10: v8@6539,2626 6562.42,2626 6599.33,2589.08 U26.47@6599.33,2569.86
  Bottom Layer w10: CEXT3.2@6399.42,2626 CEXT3.2@6409,2626 v8(6539.42,2626)
NetCEXT4_1: CEXT4.1 D2.5 D2.6 | length 155.4
  Bottom Layer w10: 6263,2567 D2.6@6279,2567 D2.5@6305,2567
  Bottom Layer w20: CEXT4.1@6213.42,2649 6213.42,2598 6244.42,2567 6263,2567
NetCEXT4_2: CEXT4.2 U26.46 | length 632
  Top Layer w10: v4(6213.42,2799.58) 6233.83,2820 6398.42,2820 6449.42,2769 6486.42,2769 6502.42,2753 6502.42,2711.46 6619.02,2594.85 U26.46@6619.02,2569.86
  Bottom Layer w10: CEXT4.2@6202,2729 6202,2788.17 v4(6213.42,2799.58)
NetD3_1: D3.1 D25.1 | length 160.9
  Top Layer w30: D25.1@2188.42,2527 2218,2527 2238,2547 D3.1@2238,2650
NetD4_1: D4.1 P1.2 U14.70 | length 1298.1
  Top Layer w12: P1.2@353.5,3976.85 458.86,3976.85 v8(491,3944.71) D4.1@491,3900.56
  Bottom Layer w10: 1494.07,4019.8 U14.70@1550.85,4019.8
  Bottom Layer w12: v8(491,3944.71) 492.29,3946 528,3946 533.29,3940.71 799.71,3940.71 832,3973 952.12,3973 994.12,4015 1377,4015 1391.16,4029.16 1484.71,4029.16 1494.07,4019.8
NetD5_1: D5.1 Q46.1 R167.1 R168.1 | length 262.5
  Top Layer w20: D5.1@6009,1990 R167.1@6009,1940 6050,1940 ; Q46.1@6050.42,1819.57 6050.42,1939.58 6050,1940 ; R168.1@6100.86,1940 6050,1940
NetD5_3: D5.3 F1.1 Q14.7 Q14.8 Q46.3 R166.2 R167.2
  other v2: 5759.5,2019.92 5809.5,2019.92 5759.5,2054.92 5809.5,2054.92 5759.5,2089.92 5809.5,2089.92
NetD9_1: D9.1 P1.3 U14.71 | length 1300
  Top Layer w12: P1.3@353.5,3945.35 353.5,3944.71 v8(443,3944.71) D9.1@443,3901
  Bottom Layer w10: 1505,4039.48 U14.71@1550.85,4039.48
  Bottom Layer w12: v8(443,3944.71) 472.29,3974 528.28,3974 541.58,3960.71 791.42,3960.71 823.72,3993 943.84,3993 985.84,4035 1368.72,4035 1382.87,4049.16 1495.32,4049.16 1505,4039.48
NetD11_1: D11.1 D50.1 F17.2 | length 201.7
  Top Layer w30: D50.1@1891,1398 D11.1@1968.53,1398 1968.53,1521.56 F17.2@1968.98,1522
NetD11_2: D11.2 D12.1 R83.2 | length 186.1
  Top Layer w30: R83.2@2087,1293 2087,1349 2097.47,1359.47 D11.2@2097.47,1398 2173.47,1398 D12.1@2174,1397.47
NetD12_2: D12.2 F18.1 | length 63.5
  Top Layer w30: F18.1@2174,1205 D12.2@2174,1268.53
NetD15_1: D15.1 R260.2 | length 239.2
  Bottom Layer w20: D15.1@6285,999.8 6285,1037 6303.04,1055.04 6334.42,1055.04 6338.68,1059.31 6427.69,1059.31 6437,1050 R260.2@6473.88,1050
NetD15_2: D15.2 R264.2 | length 56.2
  Bottom Layer w20: D15.2@6285,924.48 6340.52,924.48 R264.2@6341,924
NetD15_3: D15.3 D24.3 Q56.3 | length 236.7
  Bottom Layer w20: Q56.3@6087.4,1099.2 6087,1098.8 6087,1037 6173,1037 6206.26,1003.74 D15.3@6206.26,962.4
NetD18_1: D18.1 R59.1 | length 95.6
  Top Layer w20: R59.1@5898,863 5898.06,863.06 R59.1@5902,863.06 D18.1@5993.57,863.06
NetD22_1: D22.1 R60.1 | length 95
  Top Layer w20: R60.1@5898,1033 D22.1@5992.99,1033
NetD23_2: D23.2 T1.10 | length 404.3
  Top Layer w50: v12(1752,1994) 1752,2089.39 T1.10@1753.37,2090.76
  Bottom Layer w50: v12(1752,1994) 1897,1849 D23.2@1998.94,1849
NetD24_1: D24.1 R266.2 | length 1255.5
  MidLayer2 w20: v3(6261,871) 6261,968.5 6332.5,1040 6488,1040 6513.42,1065.42 6513.42,1165.5 6506.42,1172.5 6506.42,1272.91 6507,1273.5 6507,1410.5 6502,1415.5 6502,1444.5 6507,1449.5 6507,1524 v6(6380,1651)
  Bottom Layer w20: D24.1@6124.28,961.8 6146.2,961.8 6237,871 v3(6261,871) ; v6(6380,1651) 6388.88,1642.12 R266.2@6422,1642.12
NetD24_2: D24.2 R270.2 | length 59.7
  Bottom Layer w30: R270.2@5990,962.44 5990.64,961.8 D24.2@6049.48,961.8
NetD25_2: D25.2 Q36.5 Q36.6 Q36.7 Q36.8 Q36.9 T1.1 T1.2 T1.3 | length 662.8
  Top Layer w50: T1.3@1753.37,2561.24 T1.2@1832.11,2561.24 T1.1@1910.85,2561.24 1974.76,2561.24 2139,2397 2343.92,2397 Q36.5@2346.92,2400
  other v9: 2361.92,2440.39 2401.92,2440.39 2441.92,2440.39 2481.92,2440.39 2361.92,2480.39 2401.92,2480.39 2441.92,2480.39 2481.92,2480.39 2361.92,2520.39 2401.92,2520.39 2441.92,2520.39 2481.92,2520.39
NetD28_2: D28.2 T1.11 | length 358.8
  Top Layer w50: T1.11@1832.11,2090.76 1832.11,2145.11 1886.24,2199.24 D28.2@2114.1,2199.24
NetD46_1: D46.1 R52.1 | length 78.8
  Top Layer w20: D46.1@1007,4363.8 1007,4401 1018,4412 R52.1@1018,4438
NetD48_1: D48.1 R47.1 | length 90.6
  Top Layer w20: R47.1@862.88,4438 862.88,4403.12 876,4390 D48.1@876,4352.8
NetD50_2: D50.2 Q12.3 | length 203.7
  Top Layer w20: Q12.3@1631,1299 1717,1299 1762.06,1344.06 D50.2@1762.06,1398
NetD53_1: D53.1 Q48.3 Q55.3 R181.2 | length 1246.6
  MidLayer3 w20: v6(6247,1722) 6266,1703 6426,1703 6528,1601 v3(6550,1601)
  Bottom Layer w20: Q55.3@5951.4,1221.8 5951.8,1222.2 Q48.3@5951.8,1341.4 6113.4,1341.4 6156,1384 6156,1653 6225,1722 v6(6247,1722) 6307.44,1782.44 D53.1@6340,1782.44 ; R181.2@6506,1601.88 6546.88,1601.88 6548.88,1599.88 v3(6550,1601)
NetD64_1: D64.1 R58.1 U34.5 | length 233.3
  Top Layer w10: 1602,3082.56 1643.94,3082.56 1648.77,3077.73 U34.5@1658.83,3077.73
  Top Layer w25: R58.1@1462,3052 1462,3077 1476.24,3091.24 D64.1@1532,3091.24 1553.24,3091.24 1561.92,3082.56 1602,3082.56
NetD64_2: D64.2 Q36.4 R58.2 | length 1264.3
  Top Layer w20: v4@1462,2827 R58.2@1462,2996.88 ; R58.2@1476.5,2997 1476.74,2996.76 D64.2@1532,2996.76 ; v4(2346.42,2673) 2346.92,2673.5 Q36.4@2346.92,2609.89 Q36.4@2346.92,2608.66
  Bottom Layer w20: v4(1461,2827) 1496,2792 1780,2792 1809,2763 1888,2763 1917,2792 2039,2792 2158,2673 v4(2346.42,2673)
NetDclamp1_1: Dclamp1.1 Zener1.1 | length 116.5
  Top Layer w25: Dclamp1.1@3367.45,3236.53 Dclamp1.1@3369.98,3234 Zener1.1@3482.91,3234
NetDclamp2_1: Dclamp2.1 Zener2.1 | length 137.5
  Top Layer w35: Dclamp2.1@5562.42,3219 Zener2.1@5699.91,3219
NetF2_1: F2.1 Q16.7 Q16.8
  other v2: 5506,2342.34 5556,2342.34 5506,2377.34 5556,2377.34 5506,2412.34 5556,2412.34
NetF3_1: F3.1 Q18.7 Q18.8
  other v2: 5354,1978.34 5404,1978.34 5354,2013.34 5404,2013.34 5354,2048.34 5404,2048.34
NetF4_1: F4.1 Q19.7 Q19.8
  other v2: 5123,2342.34 5173,2342.34 5123,2377.34 5173,2377.34 5123,2412.34 5173,2412.34
NetF5_1: F5.1 Q20.7 Q20.8
  other v2: 4973,1978.67 5023,1978.67 4973,2013.67 5023,2013.67 4973,2048.67 5023,2048.67
NetF6_2: F6.2 Q21.7 Q21.8
  other v2: 4783,2342.34 4833,2342.34 4783,2377.34 4833,2377.34 4783,2412.34 4833,2412.34
NetF7_1: F7.1 Q22.7 Q22.8
  other v2: 4603,1977.99 4653,1977.99 4603,2012.99 4653,2012.99 4603,2047.99 4653,2047.99
NetF8_2: F8.2 Q1.7 Q1.8 Q23.7 Q23.8
  other v2: 4180.42,2393.34 4230.42,2393.34 4426,2421 4476,2421 4180.42,2428.34 4230.42,2428.34 4426,2456 4476,2456 4180.42,2463.34 4230.42,2463.34 4426,2491 4476,2491
NetF9_1: F9.1 Q3.7 Q3.8
  other v2: 4150.42,2028.34 4200.42,2028.34 4150.42,2063.34 4200.42,2063.34 4150.42,2098.34 4200.42,2098.34
NetF10_1: F10.1 Q5.7 Q5.8
  other v2: 3914.42,2402.34 3964.42,2402.34 3914.42,2437.34 3964.42,2437.34 3914.42,2472.34 3964.42,2472.34
NetF11_1: F11.1 Q6.7 Q6.8
  other v2: 3720.42,2028.34 3770.42,2028.34 3720.42,2063.34 3770.42,2063.34 3720.42,2098.34 3770.42,2098.34
NetF12_1: F12.1 Q7.7 Q7.8
  other v2: 3511.42,2403.34 3561.42,2403.34 3511.42,2438.34 3561.42,2438.34 3511.42,2473.34 3561.42,2473.34
NetF13_1: F13.1 Q8.7 Q8.8
  other v2: 3291.42,2028.34 3341.42,2028.34 3291.42,2063.34 3341.42,2063.34 3291.42,2098.34 3341.42,2098.34
NetF14_1: F14.1 Q9.7 Q9.8
  other v2: 3080.42,2403.34 3130.42,2403.34 3080.42,2438.34 3130.42,2438.34 3080.42,2473.34 3130.42,2473.34
NetF15_1: F15.1 Q10.7 Q10.8
  other v2: 2917.42,2028.34 2967.42,2028.34 2917.42,2063.34 2967.42,2063.34 2917.42,2098.34 2967.42,2098.34
NetF18_2: F18.2 P2.1 | length 351.7
  Top Layer w50: P2.1@2127.4,613.57 2127.4,762.4 2174,809 F18.2@2174,945 F18.2@2174,946
NetF19_2: F19.2 P2.2 | length 349.2
  Top Layer w50: F19.2@1987,946 F19.2@1987,945 1987,779 2027.4,738.6 P2.2@2027.4,613.57
NetJ2_1: J2.1 R209.2 | length 124
  Top Layer w15: v1(6072,4864) J2.1@6148,4864
  Bottom Layer w15: v1(6072,4864) R209.2@6072,4912
NetJ2_2: J2.2 R225.2 | length 124
  Top Layer w15: v1(6070,5142) J2.2@6148,5142
  Bottom Layer w15: R225.2@6070,5096 v1(6070,5142)
NetJ2_3: J2.3 R200.2 | length 90
  Top Layer w15: v1@6156,4912 6173,4895 J2.3@6173,4864
  Bottom Layer w20: R200.2@6120,4911.88 v1@6155,4911.88
  other v1: 6155,4912
NetJ2_4: J2.4 R234.2 | length 98.9
  Top Layer w15: v1(6172.88,5096) 6173,5096.12 J2.4@6173,5142
  Bottom Layer w20: R234.2@6120,5096 v1(6172.88,5096)
NetJ3_1: J3.1 R91.2 R231.2 U7.22 | length 1260.6
  Top Layer w8: U7.22@7216.09,4370.12 7242.12,4370.12 7251,4379 7397,4379 7415,4361 R231.2@7442.44,4361
  Top Layer w10: J3.1@7297,4953 7335,4991 7357,4991 7398,4950 7398,4824.06 7412.5,4809.56 7412.5,4786.5 v1(7441,4758) ; R231.2@7442.44,4361 7442.44,4302.44 R91.2@7442,4302 7531,4302 7577,4348 v1(7577,4382)
  Bottom Layer w10: v1(7441,4758) 7552.5,4646.5 7552.5,4501.44 7557.5,4496.44 7557.5,4401.5 v1(7577,4382)
NetJ3_3: J3.3 R230.2 U7.26 | length 1116.2
  Top Layer w7: U7.26@7167.87,4434.09 7168,4434.23 7168,4450.19 7175.81,4458 7220.52,4458 7263,4500.48 7263,4546.86 7273.14,4557 7295,4557 7314,4576 R230.2@7314,4606.44
  Top Layer w10: J3.3@7197,4953 7197,5022 7229,5054 7322,5054 7416,4960 7416,4832 7473,4775 7473,4753.12 7451.88,4732 7370,4732 7344,4706 7344,4614 7336.44,4606.44 R230.2@7314,4606.44
NetJ3_5: J3.5 R232.2 U7.24 | length 1237.5
  Top Layer w7: U7.24@7216.09,4401.61 7216.09,4408.09 7226,4418 7381,4418 7406,4443 7406,4493 7425,4512 R232.2@7445,4512
  Top Layer w10: J3.5@7097,4953 7216,5072 7333,5072 7442.24,4962.76 7442.24,4831.76 7491,4783 7491,4745.38 7445,4699.38 R232.2@7445,4512
NetJ3_8: J3.8 R90.2 R233.2 U7.27 | length 596.8
  Top Layer w7: U7.27@7152.12,4434.09 7152.12,4446.27 7153,4447.15 7153,4456.4 7169.6,4473 7214.3,4473 7248,4506.7 7248,4553.08 7266,4571.08 R233.2@7266,4607 7246,4607 7236,4617 R90.2@7236,4712.38
  Top Layer w10: J3.8@7197,4903 7197,4727 7211.62,4712.38 R90.2@7236,4712.38
NetJ3_9: J3.9 R229.2 U7.23 | length 991.7
  Top Layer w7: U7.23@7216.09,4385.87 7232.87,4385.87 7242,4395 7398,4395 7417,4414 R229.2@7445,4414
  Top Layer w10: J3.9@7247,4903 7247,4808 v1(7297,4758) ; R229.2@7445,4414 7445,4445 7462,4462 v1(7532,4462)
  Bottom Layer w10: v1(7297,4758) 7323,4732 7437.54,4732 7532,4637.54 v1(7532,4462)
NetJ4_1: J4.1 R84.2 | length 119
  Top Layer w15: v1(859,4750) J4.1@933,4750
  Bottom Layer w15: v1(859,4750) R84.2@859,4795
NetJ4_2: J4.2 R154.2 | length 120
  Top Layer w15: v1(859,5028) J4.2@933,5028
  Bottom Layer w15: R154.2@859,4982 v1(859,5028)
NetJ4_3: J4.3 R81.2 | length 96.2
  Top Layer w15: v1(957.56,4795.44) 957.56,4750.44 J4.3@958,4750
  Bottom Layer w15: R81.2@907,4795.44 v1(957.56,4795.44)
NetJ4_4: J4.4 R193.2 | length 97
  Top Layer w15: v1(958,4982) J4.4@958,5028
  Bottom Layer w15: R193.2@907,4982 v1(958,4982)
NetJ7_3: J7.3 R233.1 | length 5621.3
  Top Layer w10: v8(2311,4545) J7.3@2311,4716 ; R233.1@7266,4662.12 7266,4690 v1(7279,4703)
  MidLayer3 w10: v8(2311,4545) 2374.94,4545 2400.44,4570.5 2623.98,4570.5 2694.48,4500 2767.52,4500 2798,4530.48 2798,4635.19 2908.01,4745.2 3332.21,4745.2 3350.21,4727.2 3697.48,4727.2 3715.8,4745.52 3839.89,4745.52 3871.37,4777 4457.91,4777 4508.91,4828 5097,4828 5211,4714 5892.3,4714 5904.69,4726.38 6160.2,4726.38 6199.82,4766 6647.1,4766 6693.1,4720 6980,4720 7090,4610 7137,4610 7160.5,4633.5 7160.5,4654.5 7175.5,4669.5 7201.56,4669.5 7235.06,4703 v1(7279,4703)
NetJ7_11: J7.11 R77.2 | length 264.4
  Top Layer w10: J7.11@2710,4717 J7.11@2711,4716 v8(2711,4545)
  Bottom Layer w10: v8(2711,4545) R77.2@2711,4637
NetJ7_17: J7.17 R78.2 | length 264.4
  Top Layer w10: J7.17@3010,4717 J7.17@3011,4716 v8(3011,4545)
  Bottom Layer w10: v8(3011,4545) R78.2@3011,4637
NetJ7_19: J7.19 R79.2 | length 264.4
  Top Layer w10: J7.19@3110,4717 J7.19@3111,4716 v8(3111,4545)
  Bottom Layer w10: v8(3111,4545) R79.2@3111,4637
NetP3_A4: P3.A4 P3.B4 R163.2 | length 1400.9
  Top Layer w20: R163.2@876,1543.44 876,1497 988,1385 P3.B4@988,782
  MidLayer3 w20: P3.A4@438,782 490,834 936,834 P3.B4@988,782
NetP3_A5: P3.A5 P3.B5 R160.2 R252.1 | length 1523.3
  Top Layer w20: P3.A5@488,682 488,1428 558,1498 R252.1@597,1498 R160.2@597,1543.44
  MidLayer3 w20: P3.A5@488,682 541,629 985,629 P3.B5@1038,682
NetQ1_1: Q1.1 Q1.3 U6.3 | length 1321.5
  Top Layer w10: v4(4580.42,2984) 4596.42,2968 4642.43,2968 4665.28,2945.14 U6.3@4885.06,2945.14
  Top Layer w20: Q1.3@4130.42,2550 4130.42,2626 4149.42,2645 4213,2645 4230.42,2627.58 v4(4230.42,2610) Q1.1@4230.42,2550
  Bottom Layer w20: v4(4230.42,2610) 4361.42,2741 4552,2741 4665.42,2854.42 4665.42,2949 4665,2949.42 4665,2952.5 4644.5,2973 4591.42,2973 v4(4580.42,2984)
NetQ1_2: Q1.2 Q1.4 U6.4 | length 1268.8
  Top Layer w10: v4(4630,2938) 4630,2934.42 4638.96,2925.46 U6.4@4885.06,2925.46
  Top Layer w20: Q1.4@4080.42,2550 v4(4080.42,2610) ; Q1.2@4180.42,2550 v4(4180.42,2610)
  Bottom Layer w20: v4(4180.42,2610) v4(4080.42,2610) 4080.42,2702.42 4147,2769 4540.4,2769 4630.42,2859.01 4630.42,2934 4630,2934.42 v4(4630,2938)
NetQ1_5: Q1.5 Q1.6 Q2.1 Q4.5 Q4.6 Q5.5 Q5.6 Q7.5 Q7.6 Q9.5 Q9.6 U6.37 | length 1753.4
  Top Layer w10: 5010.42,3271 5030.78,3271 5167.42,3134.37 5167.42,3061 5127.18,3020.77 U6.37@5127.18,3010.1
  Top Layer w20: Q2.1@4085.75,2908 4137.42,2908 ; v20(4514.42,3296) 4531.42,3313 4617.02,3313 4660.02,3356 4840.42,3356 4896.42,3300 4940.41,3300 4969.41,3271 5010.42,3271
  Bottom Layer w20: Q4.6@4083.09,2934 4038.42,2934 4026.42,2946 4026.42,3120 4096.42,3190 4421.42,3190 v20@4514.42,3283
  other v2: 4080.42,2393.34 4130.42,2393.34 3814.42,2402.34 3864.42,2402.34 2980.42,2403.34 3030.42,2403.34 3411.42,2403.34 3461.42,2403.34 4080.42,2428.34 4130.42,2428.34 3814.42,2437.34 3864.42,2437.34 2980.42,2438.34 3030.42,2438.34 3411.42,2438.34 3461.42,2438.34 4080.42,2463.34 4130.42,2463.34 3814.42,2472.34 3864.42,2472.34 2980.42,2473.34 3030.42,2473.34 3411.42,2473.34 3461.42,2473.34 4135.09,2884 4170.09,2884 4205.09,2884 4135.09,2934 4170.09,2934 4205.09,2934
NetQ2_3: Q2.3 Q3.5 Q3.6 Q4.7 Q4.8 Q6.5 Q6.6 Q8.5 Q8.6 Q10.5 Q10.6 U6.39 | length 1523.7
  Top Layer w10: 5017.42,3215 5034.42,3215 5131.42,3118 5131.42,3075.91 5087.81,3032.31 U6.39@5087.81,3010.1
  Top Layer w20: Q2.3@4085.75,3008 4137.42,3008 ; v20(4514.42,3225) 4548.82,3225 4580.82,3257 4640.22,3257 4683.22,3300 4817.22,3300 4873.22,3244 4917.21,3244 4946.21,3215 5017.42,3215
  Bottom Layer w20: Q4.8@4145.09,3009 4145.09,3063.68 4154.42,3073 4511.42,3073 4550.42,3112 4550.42,3214 4539.42,3225 v20(4514.42,3225)
  other v2: 2817.42,2028.34 2867.42,2028.34 3191.42,2028.34 3241.42,2028.34 3620.42,2028.34 3670.42,2028.34 4050.42,2028.34 4100.42,2028.34 2817.42,2063.34 2867.42,2063.34 3191.42,2063.34 3241.42,2063.34 3620.42,2063.34 3670.42,2063.34 4050.42,2063.34 4100.42,2063.34 2817.42,2098.34 2867.42,2098.34 3191.42,2098.34 3241.42,2098.34 3620.42,2098.34 3670.42,2098.34 4050.42,2098.34 4100.42,2098.34 4135.09,2984 4170.09,2984 4205.09,2984 4135.09,3034 4170.09,3034 4205.09,3034
NetQ3_1: Q3.1 Q3.3 U6.5 | length 1847
  Top Layer w10: v4(4580.42,2934) 4607.01,2907.4 4629.3,2907.4 4632.61,2904.09 4710.5,2904.09 4712.19,2905.77 U6.5@4885.06,2905.77
  Top Layer w20: Q3.3@4100.42,2185 4100.42,2261 4119.42,2280 4183,2280 4200.42,2262.58 v4(4200.42,2245) Q3.1@4200.42,2185
  Bottom Layer w20: v4(4200.42,2245) 4200.42,2314.58 4155,2360 4076.41,2360 4045,2391.41 4045,2707 4135,2797 4528.8,2797 4591,2859.2 4591,2906 4580.42,2916.58 v4(4580.42,2934)
NetQ3_2: Q3.2 Q3.4 U6.6 | length 1665.8
  Top Layer w10: v4(4550.42,2884) 4597.39,2884 4602.79,2889.4 4621.84,2889.4 4625.16,2886.09 U6.6@4885.06,2886.09
  Top Layer w20: Q3.4@4050.42,2185 v4(4050.42,2245) ; Q3.2@4150.42,2185 v4(4150.42,2245)
  Bottom Layer w20: v4(4150.42,2245) v4(4050.42,2245) 4015,2280.42 4015,2719 4121,2825 4517.21,2825 4550.42,2858.21 v4(4550.42,2884)
NetQ5_1: Q5.1 Q5.3 U6.7 | length 1401.3
  Top Layer w10: 4612.31,2866.4 U6.7@4885.06,2866.4
  Top Layer w20: Q5.3@3864.42,2559 3864.42,2635 3883.42,2654 3947,2654 3964.42,2636.58 v4(3964.42,2619) Q5.1@3964.42,2559 ; v4(4000.42,2832) 4034.42,2832 4041.42,2825 4570.91,2825 4612.31,2866.4
  Bottom Layer w20: v4(3964.42,2619) 3964.42,2796 v4(4000.42,2832)
NetQ5_2: Q5.2 Q5.4 U6.8 | length 1399.1
  Top Layer w10: 4621.51,2836 4632.23,2846.72 U6.8@4885.06,2846.72
  Top Layer w20: Q5.4@3814.42,2559 v4(3814.42,2619) ; Q5.2@3914.42,2559 v4(3914.42,2619) ; v4(3914.42,2804) 3915.42,2803 3947.42,2803 3953.42,2797 4582.51,2797 4621.51,2836
  Bottom Layer w20: v4(3814.42,2619) v4(3914.42,2619) v4(3914.42,2804)
NetQ6_1: Q6.1 Q6.3 U6.9 | length 1906.1
  Top Layer w10: 4641.05,2815.95 4652.14,2827.03 U6.9@4885.06,2827.03
  Top Layer w20: Q6.3@3670.42,2185 3670.42,2261 3689.42,2280 3753,2280 3770.42,2262.58 v4(3770.42,2245) Q6.1@3770.42,2185 ; v3(3859.42,2788) 3878.42,2769 4594.11,2769 4641.05,2815.95
  Bottom Layer w20: v4(3770.42,2245) 3770.42,2646.42 3859.42,2735.42 v3(3859.42,2788)
NetQ6_2: Q6.2 Q6.4 U6.10 | length 1863
  Top Layer w10: 4658.71,2794 4672.05,2807.35 U6.10@4885.06,2807.35
  Top Layer w20: Q6.4@3620.42,2185 v4(3620.42,2245) ; Q6.2@3720.42,2185 v4(3720.42,2245) ; v3(3814.42,2748) 3838,2748 3845,2741 4605.71,2741 4658.71,2794
  Bottom Layer w20: v4(3620.42,2245) v4(3720.42,2245) 3720.42,2654 v3(3814.42,2748)
NetQ7_1: Q7.1 Q7.3 U6.11 | length 1722.6
  Top Layer w10: 4681.15,2776.85 4691.97,2787.66 U6.11@4885.06,2787.66
  Top Layer w20: Q7.3@3461.42,2560 3461.42,2636 3480.42,2655 3544,2655 3561.42,2637.58 v4(3561.42,2620) Q7.1@3561.42,2560 ; v3(3764.42,2748) 3764.42,2729.58 3781,2713 4617.31,2713 4681.15,2776.85
  Bottom Layer w20: v4(3561.42,2620) 3561.42,2656 3653.42,2748 v3(3764.42,2748)
NetQ7_2: Q7.2 Q7.4 U6.12 | length 1779.5
  Top Layer w10: 4703,2759 4711.98,2767.98 U6.12@4885.06,2767.98
  Top Layer w20: Q7.4@3411.42,2560 v4(3411.42,2620) 3411.42,2662 3434.42,2685 4629,2685 4703,2759 ; Q7.2@3511.42,2560 v4(3511.42,2620)
  Bottom Layer w20: v4(3411.42,2620) v4(3511.42,2620)
NetQ8_1: Q8.1 Q8.3 U6.14 | length 2331.3
  Top Layer w10: v4(4842,2737) 4870.46,2737 4892.46,2715 4918.38,2715 4930.33,2726.95 U6.14@4930.33,2742.39
  Top Layer w20: Q8.3@3241.42,2185 3241.42,2261 3260.42,2280 3324,2280 3341.42,2262.58 v4(3341.42,2245) Q8.1@3341.42,2185
  Bottom Layer w20: v4(3341.42,2245) 3376.42,2210 4217,2210 4239,2232 4239,2334.83 4256.42,2352.24 4256.42,2583.42 4386,2713 4564,2713 4607,2756 4823,2756 v4(4842,2737)
NetQ8_2: Q8.2 Q8.4 U6.15 | length 2382.7
  Top Layer w10: v4(4724,2719) 4803,2719 4815,2707 4873.45,2707 4883.45,2697 4925.84,2697 4950.02,2721.18 U6.15@4950.02,2742.39
  Top Layer w20: Q8.4@3191.42,2185 v4(3191.42,2245) ; Q8.2@3291.42,2185 v4(3291.42,2245)
  Bottom Layer w20: v4(3191.42,2245) v4(3291.42,2245) 3291.42,2211.58 3321,2182 4228.6,2182 4267,2220.4 4267,2323.23 4285.42,2341.64 4285.42,2572.82 4397.6,2685 4576,2685 4610,2719 v4(4724,2719)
